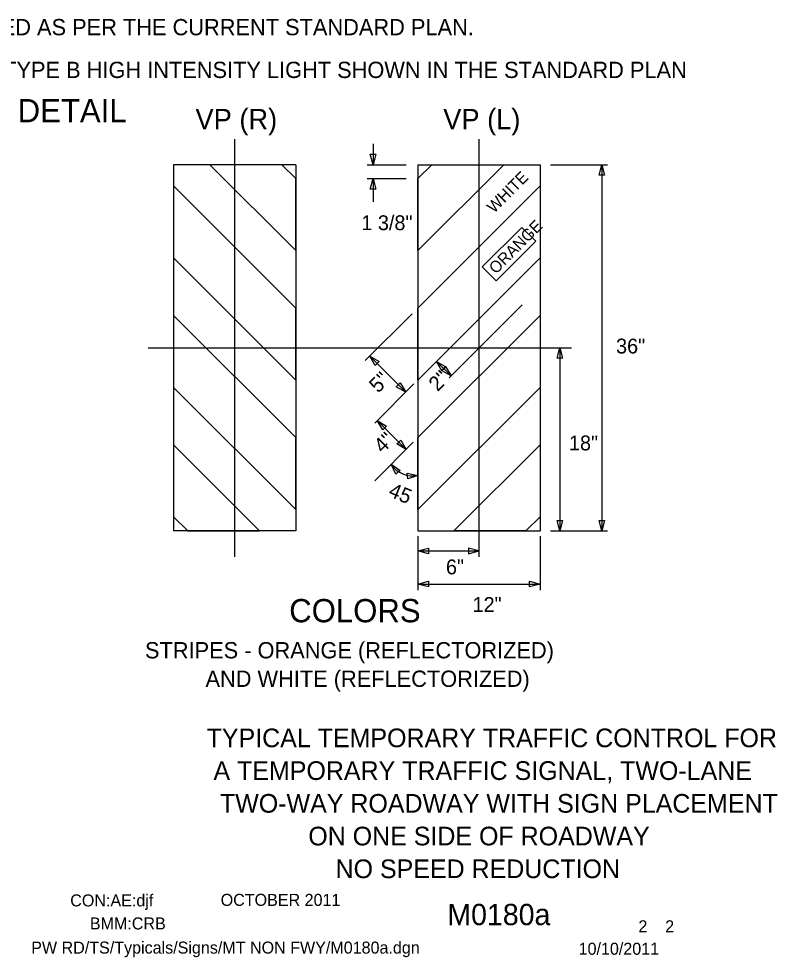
# Model space of a CAD drawing. Extents: x 16733 to 18484, y 7218 to 8208.
# Drawn here: x 18093.1 to 18484.4, y 7218.1 to 7702.3 of the extents above; entities that cross this region are included whole.
import ezdxf

# ---------------------------------------------------------------- set-up
doc = ezdxf.new("R2010")
doc.units = 0
for name, color, linetype in [('BORDER', 7, 'Continuous'), ('BORDER_SIGNAL_WO', 7, 'Continuous'), ('TRAFFIC_SIGNS_PR', 7, 'Continuous'), ('TYPICAL_TEXT_DIMEN_PR', 7, 'Continuous')]:
    doc.layers.add(name, color=color, linetype=linetype)

msp = doc.modelspace()

# ---------------------------------------------------------------- linework, layer by layer
at = {"layer": 'TRAFFIC_SIGNS_PR'}
for p, q in [((18235.99, 7627.03), (18172.99, 7627.03)), ((18172.99, 7627.03), (18172.99, 7438.03)), ((18235.99, 7582.76), (18191.73, 7627.03)), ((18235.99, 7619.89), (18228.85, 7627.03)), ((18235.99, 7627.03), (18235.99, 7438.03)), ((18299.02, 7627.03), (18362.02, 7627.03)), ((18299.02, 7627.03), (18299.02, 7438.03)), ((18299.02, 7619.89), (18306.16, 7627.03)), ((18299.02, 7582.76), (18343.29, 7627.03)), ((18362.02, 7627.03), (18362.02, 7438.03)), ((18235.99, 7553.07), (18172.99, 7616.07)), ((18299.02, 7553.07), (18362.02, 7616.07)), ((18235.99, 7515.94), (18172.99, 7578.94)), ((18299.02, 7515.94), (18362.02, 7578.94)), ((18308.3, 7562.35), (18317.58, 7571.63)), ((18235.99, 7486.25), (18172.99, 7549.25)), ((18299.02, 7486.25), (18362.02, 7549.25)), ((18235.99, 7449.12), (18172.99, 7512.12)), ((18299.02, 7449.12), (18362.02, 7512.12)), ((18217.39, 7438.03), (18172.99, 7482.42)), ((18317.63, 7438.03), (18362.02, 7482.42)), ((18180.26, 7438.03), (18172.99, 7445.3)), ((18354.75, 7438.03), (18362.02, 7445.3)), ((18235.99, 7438.03), (18172.99, 7438.03)), ((18299.02, 7438.03), (18362.02, 7438.03))]:
    msp.add_line(p, q, dxfattribs=at)
for points in [[(18228.85, 7627.03), (18191.73, 7627.03), (18235.99, 7582.76), (18235.99, 7619.89)], [(18306.16, 7627.03), (18343.29, 7627.03), (18299.02, 7582.76), (18299.02, 7619.89)], [(18235.99, 7553.07), (18172.99, 7616.07), (18172.99, 7578.94), (18235.99, 7515.94)], [(18299.02, 7553.07), (18362.02, 7616.07), (18362.02, 7578.94), (18299.02, 7515.94)], [(18235.99, 7486.25), (18172.99, 7549.25), (18172.99, 7512.12), (18235.99, 7449.12)], [(18299.02, 7486.25), (18362.02, 7549.25), (18362.02, 7512.12), (18299.02, 7449.12)], [(18172.99, 7482.42), (18172.99, 7445.3), (18180.26, 7438.03), (18217.39, 7438.03)], [(18362.02, 7482.42), (18362.02, 7445.3), (18354.75, 7438.03), (18317.63, 7438.03)]]:
    msp.add_lwpolyline(points, close=True, dxfattribs=at)
at = {"layer": 'TYPICAL_TEXT_DIMEN_PR'}
for p, q in [((18204.49, 7640.16), (18204.49, 7424.63)), ((18275.92, 7637.88), (18275.92, 7627.03)), ((18330.52, 7640.16), (18330.52, 7424.63)), ((18275.92, 7627.03), (18274.48, 7632.42)), ((18274.48, 7632.42), (18275.92, 7632.42)), ((18275.92, 7632.42), (18277.36, 7632.42)), ((18277.36, 7632.42), (18275.92, 7627.03)), ((18272.77, 7627.03), (18292.93, 7627.03)), ((18367.39, 7627.03), (18396.81, 7627.03)), ((18392.44, 7621.64), (18393.89, 7627.03)), ((18393.89, 7627.03), (18393.89, 7438.03)), ((18393.89, 7627.03), (18395.33, 7621.64)), ((18272.77, 7619.89), (18292.93, 7619.89)), ((18274.48, 7614.5), (18275.92, 7619.89)), ((18275.92, 7619.89), (18275.92, 7607.83)), ((18275.92, 7619.89), (18277.36, 7614.5)), ((18393.89, 7621.64), (18392.44, 7621.64)), ((18395.33, 7621.64), (18393.89, 7621.64)), ((18275.92, 7614.5), (18274.48, 7614.5)), ((18277.36, 7614.5), (18275.92, 7614.5)), ((18315.08, 7517.08), (18352.8, 7554.81)), ((18271.9, 7525.95), (18296.09, 7550.14)), ((18159.87, 7532.53), (18378.29, 7532.53)), ((18370.78, 7527.14), (18372.22, 7532.53)), ((18372.22, 7532.53), (18372.22, 7438.03)), ((18372.22, 7532.53), (18373.67, 7527.14)), ((18292.72, 7509.64), (18274.16, 7528.21)), ((18276.95, 7523.38), (18274.16, 7528.21)), ((18274.16, 7528.21), (18278.99, 7525.42)), ((18278.99, 7525.42), (18277.97, 7524.4)), ((18316.1, 7518.1), (18308.64, 7525.56)), ((18311.43, 7520.73), (18308.64, 7525.56)), ((18308.64, 7525.56), (18313.47, 7522.78)), ((18372.22, 7527.14), (18370.78, 7527.14)), ((18373.67, 7527.14), (18372.22, 7527.14)), ((18277.97, 7524.4), (18276.95, 7523.38)), ((18311.27, 7520.89), (18312.29, 7521.91)), ((18316.1, 7518.1), (18311.27, 7520.89)), ((18312.45, 7521.75), (18311.43, 7520.73)), ((18312.29, 7521.91), (18313.31, 7522.93)), ((18313.47, 7522.78), (18312.45, 7521.75)), ((18313.31, 7522.93), (18316.1, 7518.1)), ((18276.74, 7493.66), (18296.97, 7513.89)), ((18287.89, 7512.43), (18288.91, 7513.45)), ((18292.72, 7509.64), (18287.89, 7512.43)), ((18288.91, 7513.45), (18289.93, 7514.47)), ((18289.93, 7514.47), (18292.72, 7509.64)), ((18292.92, 7480.15), (18278.07, 7494.99)), ((18280.86, 7490.16), (18278.07, 7494.99)), ((18278.07, 7494.99), (18282.9, 7492.2)), ((18282.9, 7492.2), (18281.88, 7491.19)), ((18281.88, 7491.19), (18280.86, 7490.16)), ((18276.74, 7463.97), (18296.62, 7483.85)), ((18288.09, 7482.93), (18289.11, 7483.95)), ((18292.92, 7480.15), (18288.09, 7482.93)), ((18289.11, 7483.95), (18290.13, 7484.98)), ((18290.13, 7484.98), (18292.92, 7480.15)), ((18287.62, 7467.42), (18285.23, 7472.45)), ((18285.23, 7472.45), (18289.82, 7469.29)), ((18288.72, 7468.35), (18287.62, 7467.42)), ((18289.82, 7469.29), (18288.72, 7468.35)), ((18293.65, 7466.39), (18293.55, 7467.83)), ((18293.55, 7467.83), (18299.02, 7466.74)), ((18293.74, 7464.95), (18293.65, 7466.39)), ((18299.02, 7466.74), (18293.74, 7464.95)), ((18372.22, 7438.03), (18370.78, 7443.42)), ((18370.78, 7443.42), (18372.22, 7443.42)), ((18372.22, 7443.42), (18373.67, 7443.42)), ((18373.67, 7443.42), (18372.22, 7438.03)), ((18393.89, 7438.03), (18392.44, 7443.42)), ((18392.44, 7443.42), (18393.89, 7443.42)), ((18393.89, 7443.42), (18395.33, 7443.42)), ((18395.33, 7443.42), (18393.89, 7438.03)), ((18299.02, 7435.41), (18299.02, 7407.43)), ((18362.02, 7435.41), (18362.02, 7407.43)), ((18367.39, 7438.03), (18396.81, 7438.03)), ((18299.02, 7427.77), (18304.41, 7429.22)), ((18304.41, 7429.22), (18304.41, 7427.77)), ((18330.52, 7427.77), (18325.13, 7429.22)), ((18325.13, 7429.22), (18325.13, 7427.77)), ((18299.02, 7427.77), (18330.52, 7427.77)), ((18304.41, 7426.33), (18299.02, 7427.77)), ((18304.41, 7427.77), (18304.41, 7426.33)), ((18325.13, 7427.77), (18325.13, 7426.33)), ((18325.13, 7426.33), (18330.52, 7427.77)), ((18299.02, 7410.62), (18304.41, 7412.06)), ((18299.02, 7410.62), (18362.02, 7410.62)), ((18304.41, 7409.17), (18299.02, 7410.62)), ((18304.41, 7412.06), (18304.41, 7410.62)), ((18304.41, 7410.62), (18304.41, 7409.17)), ((18356.63, 7410.62), (18356.63, 7412.06)), ((18356.63, 7412.06), (18362.02, 7410.62)), ((18362.02, 7410.62), (18356.63, 7409.17)), ((18356.63, 7409.17), (18356.63, 7410.62))]:
    msp.add_line(p, q, dxfattribs=at)
msp.add_lwpolyline([(18332.19, 7574.28), (18352.61, 7594.71), (18359.79, 7587.52), (18339.37, 7567.1)], close=True, dxfattribs=at)
msp.add_arc((18296.26, 7479.57), 13.12, 212.8393, 282.1565, dxfattribs=at)

# ---------------------------------------------------------------- texts
at = {"layer": 'BORDER'}
for s, p in [('TYPICAL TEMPORARY TRAFFIC CONTROL FOR', (18190.04, 7326.46)), ('A TEMPORARY TRAFFIC SIGNAL, TWO-LANE', (18193.56, 7309.57)), ('TWO-WAY ROADWAY WITH SIGN PLACEMENT', (18196.92, 7292.68)), ('ON ONE SIDE OF ROADWAY', (18242.49, 7275.8)), ('NO SPEED REDUCTION', (18256.54, 7258.91))]:
    msp.add_text(s, height=9.6347, dxfattribs=at).set_placement(p)
at = {"layer": 'BORDER_SIGNAL_WO'}
for s, height, p in [('CON:AE:djf', 6.2, (18119.69, 7244.31)), ('    OCTOBER 2011    ', 6.2, (18188.08, 7244.59)), ('    M0180a    ', 11, (18297.86, 7234.63)), ('BMM:CRB   ', 6.2, (18129.81, 7232.42)), (' 2    2 ', 6.2, (18410.45, 7230.95)), ('PW RD/TS/Typicals/Signs/MT NON FWY/M0180a.dgn     ', 6.2, (18099.55, 7219.96)), ('10/10/2011    ', 6.2, (18381.93, 7219.38))]:
    msp.add_text(s, height=height, dxfattribs=at).set_placement(p)
at = {"layer": 'TYPICAL_TEXT_DIMEN_PR'}
for s, height, p in [('TEMPORARY CONCRETE BARRIER SHALL BE APPLIED AS PER THE CURRENT STANDARD PLAN.', 8.4, (17801.7, 7693.82)), ('VERTICAL PANELS SHALL BE USED IN LIEU OF THE TYPE B HIGH INTENSITY LIGHT SHOWN IN THE STANDARD PLAN ', 8.4, (17801.7, 7671.77)), ('SIGN DETAIL', 12, (18048.89, 7648.94)), ('VP (R)', 10.5, (18184.3, 7645.33)), ('VP (L)', 10.5, (18312.1, 7645.33)), ('1 3/8"', 7.654, (18269.84, 7593.26)), ('36"', 7.654, (18401.23, 7529.62)), ('18"', 7.654, (18376.93, 7479.63)), ('6"', 7.654, (18313.48, 7415.67)), ('COLORS', 12, (18232.64, 7390.93)), ('12"', 7.654, (18327.19, 7396.27)), ('STRIPES - ORANGE (REFLECTORIZED)', 8.4, (18158.25, 7372.3)), ('          AND WHITE (REFLECTORIZED)', 8.4, (18158.25, 7357.6))]:
    msp.add_text(s, height=height, dxfattribs=at).set_placement(p)
for s, height, rotation, p in [('WHITE', 6, 45, (18338.21, 7601.7)), ('ORANGE', 6, 45, (18339.24, 7570.26)), ('5"', 7.654, 45, (18278.49, 7508.84)), ('2"', 7.654, 45.0095, (18309.18, 7509.58)), ('4"', 7.654, 45, (18280.84, 7477.73)), ('45', 7.655, 337.5007, (18283.31, 7456.13))]:
    msp.add_text(s, height=height, rotation=rotation, dxfattribs=at).set_placement(p)

doc.saveas('drawing.dxf')
